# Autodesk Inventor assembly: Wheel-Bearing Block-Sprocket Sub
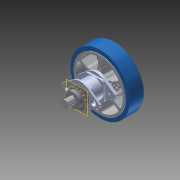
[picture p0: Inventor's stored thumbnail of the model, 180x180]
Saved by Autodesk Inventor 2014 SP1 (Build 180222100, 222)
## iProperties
Created: 2014-09
Part Number: Wheel-Bearing Block-Sprocket Sub
Document SubType Name: Assembly
Designer: Michael
Mass: 358.716 g
Surface Area: 791.74 cm^2
Volume: 161.244 cm^3
Density: 2.22467 g/cm^3
Author: Michael
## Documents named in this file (7)
- C:\Users\Michael\Documents\Inventor\6 CIM V2\Wheel-Bearing Block-Sprocket Sub.iam
- C:\Users\Michael\Documents\Inventor\6 CIM V2\217-3436-STEP.iam
- C:\Users\Michael\Documents\Inventor\6 CIM V2\217-2731.20121205.ipt
- C:\Users\Michael\Documents\Inventor\6 CIM V2\4 Perf ThruTread 500 Key.ipt
- C:\Users\Michael\Documents\Inventor\6 CIM V2\Blue Nitrile Tread.ipt
- C:\Users\Michael\Documents\Inventor\6 CIM V2\217-2643.20121204.ipt
- C:\Users\Michael\Documents\Inventor\6 CIM V2\Outer Wheel Shaft.ipt
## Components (7 placed, 6 different names)
1. 217-3436-STEP:1 [sub-assembly] — Mate:8, Flush:1, Mate:9, Mate:10
2. 217-2731.20121205:1
3. 217-2731.20121205:2
4. 4 Perf ThruTread 500 Key:1 — Mate:8, Flush:1, Flush:2, Angle:1
5. Blue Nitrile Tread:1
6. 217-2643.20121204:1 — Mate:9
7. Outer Wheel Shaft:1 — Mate:10, Flush:2
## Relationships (6: Mate 3, Flush 2, Angle 1)
- Mate:8: 217-3436-STEP:1 ↔ 4 Perf ThruTread 500 Key:1
- Flush:1: 217-3436-STEP:1 ↔ 4 Perf ThruTread 500 Key:1
- Mate:9: 217-3436-STEP:1 ↔ 217-2643.20121204:1
- Mate:10: 217-3436-STEP:1 ↔ Outer Wheel Shaft:1
- Flush:2: 4 Perf ThruTread 500 Key:1 ↔ Outer Wheel Shaft:1
- Angle:1: 4 Perf ThruTread 500 Key:1
